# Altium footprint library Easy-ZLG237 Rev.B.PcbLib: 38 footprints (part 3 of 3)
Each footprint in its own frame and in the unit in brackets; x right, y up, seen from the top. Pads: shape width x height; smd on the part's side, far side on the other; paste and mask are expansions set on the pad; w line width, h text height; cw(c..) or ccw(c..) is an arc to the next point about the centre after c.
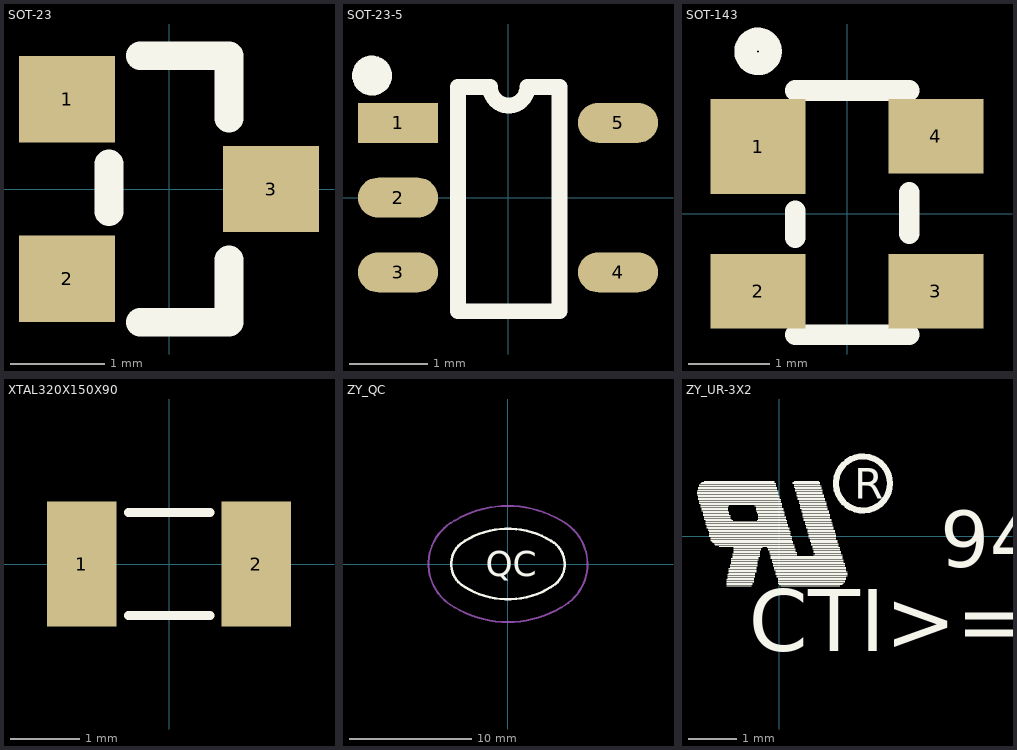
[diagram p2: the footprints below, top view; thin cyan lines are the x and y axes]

## SOT-23 [mil]
height 7.87
pads (3):
  rect 40x36 smd: 1(-42.5,37.4) 2(-42.5,-37.4) 3(42.5,0)
Top Overlay:
  lines w12: -25,-9.5 -25,10.5 ; -12,-55.5 25,-55.5 25,-29.5 ; -12,55.5 25,55.5 25,29.5
3D body "sot23-3.STEP": height 39.37, standoff -0.79, extent -47,-56.98 50.48,57.98

## SOT-23-5 [mil]
pads (5):
  rect 40x20 smd: 1(-55,37.4)
  oval 40x20 smd: 2(-55,0) 3(-55,-37.4) 4(55,-37.4) 5(55,37.4)
Top Overlay:
  circle w10: c-68,61 r5
  lines w7.87: -25,55.4 -25,-56.8 25.7,-56.8 25.7,55.4 ; -9,55.4 ccw(c0.35,55.4) 9.7,55.4
  lines w8: -25,55.4 -9,55.4 ; 9.7,55.4 25.7,55.4
3D body "User Library-SOT23-5.STEP": height 42.79, standoff -0.51, extent -55.16,-57.06 55.09,57.09

## SOT-143 [mil] "SOT-143B"
pads (4):
  rect 46x46 smd: 1(-43,32.5)
  rect 46x36 smd: 2(-43,-37.5) 3(43,-37.5) 4(43,37.5)
Top Overlay:
  circle w11: c-43,78.5 r6
  lines w10: -25,-58.5 30.12,-58.5 ; -25,-11.5 -25,1.5 ; -25,59.61 30.12,59.61 ; 30.12,-9.5 30.12,10.5

## XTAL320X150X90 [mm]
height 0.9
pads (2):
  rect 1x1.8 smd: 1(-1.253,0) 2(1.25,0)
Top Overlay:
  lines w0.127: -0.584,-0.737 0.584,-0.737 ; -0.584,0.737 0.584,0.737

## ZY_QC [mm]
height 0.051
Top Overlay:
  lines w0.203: -3.878,1.647 ccw(c-2.489,0) -3.866,-1.657 ; -3.878,1.647 cw(c0,-3.759) 3.528,1.882 ; -3.866,-1.656 ccw(c0,3.759) 3.878,-1.647 ; 3.55,1.875 cw(c2.489,0) 3.878,-1.647
  text "QC" at -1.803,-1.019 h2.06
Mechanical 15:
  lines w0.152: -4.369,3.543 ccw(c-2.489,0) -4.362,-3.547 ; -4.36,-3.545 ccw(c0.005,3.759) 4.364,-3.549 ; -4.359,3.549 cw(c0,-3.759) 4.312,3.577 ; 4.311,3.576 cw(c2.494,0) 4.374,-3.543

## ZY_UR-3X2 [mm]
height 0.2
Top Overlay:
  drawing of 193 lines, arcs and shapes, not listed
  text "CTI>=175" at -0.635,-2.794 h2.2
  text "R" at 1.549,0.775 h0.64
  text "94V-0" at 3.327,-0.635 h1.17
